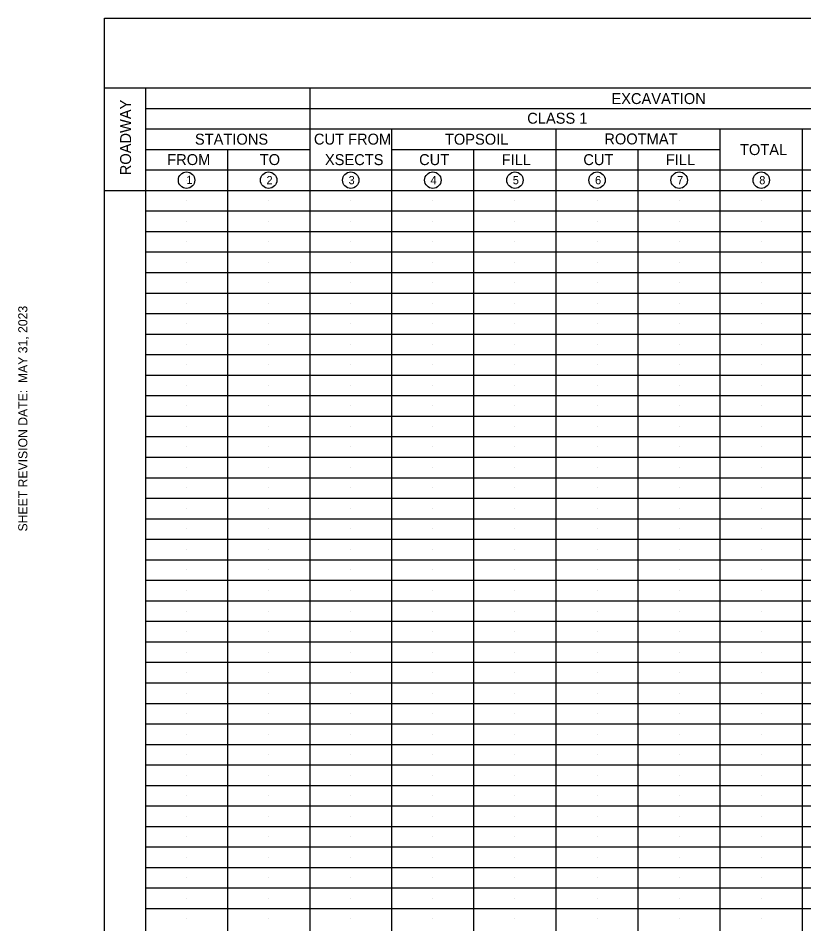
# Model space of a CAD drawing. Extents: x 1.3 to 38.6, y 0 to 21.1.
# Drawn here: x 1.3 to 9.92, y 11.12 to 21.06 of the extents above; entities that cross this region are included whole.
import ezdxf

# ---------------------------------------------------------------- set-up
doc = ezdxf.new("R2010")
doc.units = 0
for name, color, linetype in [('BORD-LINE', 7, 'Continuous'), ('CONS-LOGO', 7, 'Continuous'), ('TTLB-TEXT', 7, 'Continuous'), ('USER-LINE', 7, 'Continuous')]:
    doc.layers.add(name, color=color, linetype=linetype)

msp = doc.modelspace()

# ---------------------------------------------------------------- linework, layer by layer
at = {"layer": 'CONS-LOGO'}
for centre in [(3.1479, 19.278), (4.0479, 19.278), (4.9479, 19.278), (5.8479, 19.278), (6.7479, 19.278), (7.6479, 19.278), (8.5479, 19.278), (9.4479, 19.278)]:
    msp.add_circle(centre, 0.09, dxfattribs=at)
at = {"layer": 'TTLB-TEXT'}
for p, q in [((2.248, 1.1651), (2.248, 21.0551)), ((2.248, 21.055), (22.498, 21.055)), ((2.248, 20.29), (2.249, 20.29)), ((2.248, 20.29), (22.498, 20.29)), ((2.698, 20.29), (2.698, 1.165)), ((4.498, 20.2901), (4.498, 1.1651)), ((2.698, 20.065), (17.098, 20.065)), ((2.698, 19.84), (22.498, 19.84)), ((5.398, 4.54), (5.398, 19.8401)), ((7.198, 4.54), (7.198, 19.8401)), ((8.998, 4.54), (8.998, 19.8401)), ((9.898, 19.8401), (9.898, 4.54)), ((2.698, 19.615), (4.498, 19.615)), ((3.598, 19.6151), (3.598, 17.815)), ((5.398, 19.615), (8.998, 19.615)), ((6.298, 4.54), (6.298, 19.6151)), ((8.098, 4.54), (8.098, 19.6151)), ((2.698, 19.39), (22.498, 19.39)), ((2.248, 19.165), (22.498, 19.165)), ((2.698, 18.94), (22.498, 18.94)), ((2.698, 18.715), (22.498, 18.715)), ((2.698, 18.49), (22.498, 18.49)), ((2.698, 18.265), (22.498, 18.265)), ((2.698, 18.04), (22.498, 18.04)), ((2.698, 17.815), (22.498, 17.815)), ((3.598, 17.815), (3.598, 17.59)), ((2.698, 17.59), (22.498, 17.59)), ((3.598, 17.59), (3.598, 16.915)), ((2.698, 17.365), (22.498, 17.365)), ((2.698, 17.14), (22.498, 17.14)), ((2.698, 16.915), (22.498, 16.915)), ((3.598, 16.915), (3.598, 14.665)), ((2.698, 16.69), (22.498, 16.69)), ((2.698, 16.465), (22.498, 16.465)), ((2.698, 16.24), (22.498, 16.24)), ((2.698, 16.015), (22.498, 16.015)), ((2.698, 15.79), (22.498, 15.79)), ((2.698, 15.565), (22.498, 15.565)), ((2.698, 15.34), (22.498, 15.34)), ((2.698, 15.115), (22.498, 15.115)), ((2.698, 14.89), (22.498, 14.89)), ((2.698, 14.665), (22.498, 14.665)), ((3.598, 14.665), (3.598, 1.165)), ((2.698, 14.44), (22.498, 14.44)), ((2.698, 14.215), (22.498, 14.215)), ((2.698, 13.99), (22.498, 13.99)), ((2.698, 13.765), (22.498, 13.765)), ((2.698, 13.54), (22.498, 13.54)), ((2.698, 13.315), (22.498, 13.315)), ((2.698, 13.09), (22.498, 13.09)), ((2.698, 12.865), (22.498, 12.865)), ((2.698, 12.64), (22.498, 12.64)), ((2.698, 12.415), (22.498, 12.415)), ((2.698, 12.19), (22.498, 12.19)), ((2.698, 11.965), (22.498, 11.965)), ((2.698, 11.74), (22.498, 11.74)), ((2.698, 11.515), (22.498, 11.515)), ((2.698, 11.29), (22.498, 11.29))]:
    msp.add_line(p, q, dxfattribs=at)
at = {"layer": 'USER-LINE'}
for p, q in [((3.148, 19.5025), (3.148, 19.5025)), ((4.048, 19.5025), (4.048, 19.5025)), ((5.848, 19.5025), (5.848, 19.5025)), ((6.748, 19.5025), (6.748, 19.5025)), ((7.648, 19.5025), (7.648, 19.5025)), ((8.548, 19.5025), (8.548, 19.5025)), ((3.148, 19.2775), (3.148, 19.2775)), ((4.048, 19.2775), (4.048, 19.2775)), ((4.948, 19.2775), (4.948, 19.2775)), ((5.848, 19.2775), (5.848, 19.2775)), ((6.748, 19.2775), (6.748, 19.2775)), ((7.648, 19.2775), (7.648, 19.2775)), ((8.548, 19.2775), (8.548, 19.2775)), ((9.448, 19.2775), (9.448, 19.2775)), ((3.148, 19.0525), (3.148, 19.0525)), ((4.048, 19.0525), (4.048, 19.0525)), ((4.948, 19.0525), (4.948, 19.0525)), ((5.848, 19.0525), (5.848, 19.0525)), ((6.748, 19.0525), (6.748, 19.0525)), ((7.648, 19.0525), (7.648, 19.0525)), ((8.548, 19.0525), (8.548, 19.0525)), ((9.448, 19.0525), (9.448, 19.0525)), ((3.148, 18.8275), (3.148, 18.8275)), ((4.048, 18.8275), (4.048, 18.8275)), ((4.948, 18.8275), (4.948, 18.8275)), ((5.848, 18.8275), (5.848, 18.8275)), ((6.748, 18.8275), (6.748, 18.8275)), ((7.648, 18.8275), (7.648, 18.8275)), ((8.548, 18.8275), (8.548, 18.8275)), ((9.448, 18.8275), (9.448, 18.8275)), ((3.148, 18.6025), (3.148, 18.6025)), ((4.048, 18.6025), (4.048, 18.6025)), ((4.948, 18.6025), (4.948, 18.6025)), ((5.848, 18.6025), (5.848, 18.6025)), ((6.748, 18.6025), (6.748, 18.6025)), ((7.648, 18.6025), (7.648, 18.6025)), ((8.548, 18.6025), (8.548, 18.6025)), ((9.448, 18.6025), (9.448, 18.6025)), ((3.148, 18.3775), (3.148, 18.3775)), ((4.048, 18.3775), (4.048, 18.3775)), ((4.948, 18.3775), (4.948, 18.3775)), ((5.848, 18.3775), (5.848, 18.3775)), ((6.748, 18.3775), (6.748, 18.3775)), ((7.648, 18.3775), (7.648, 18.3775)), ((8.548, 18.3775), (8.548, 18.3775)), ((9.448, 18.3775), (9.448, 18.3775)), ((3.148, 18.1525), (3.148, 18.1525)), ((4.048, 18.1525), (4.048, 18.1525)), ((4.948, 18.1525), (4.948, 18.1525)), ((5.848, 18.1525), (5.848, 18.1525)), ((6.748, 18.1525), (6.748, 18.1525)), ((7.648, 18.1525), (7.648, 18.1525)), ((8.548, 18.1525), (8.548, 18.1525)), ((9.448, 18.1525), (9.448, 18.1525)), ((3.148, 17.9275), (3.148, 17.9275)), ((4.048, 17.9275), (4.048, 17.9275)), ((4.948, 17.9275), (4.948, 17.9275)), ((5.848, 17.9275), (5.848, 17.9275)), ((6.748, 17.9275), (6.748, 17.9275)), ((7.648, 17.9275), (7.648, 17.9275)), ((8.548, 17.9275), (8.548, 17.9275)), ((9.448, 17.9275), (9.448, 17.9275)), ((3.148, 17.7025), (3.148, 17.7025)), ((4.048, 17.7025), (4.048, 17.7025)), ((4.948, 17.7025), (4.948, 17.7025)), ((5.848, 17.7025), (5.848, 17.7025)), ((6.748, 17.7025), (6.748, 17.7025)), ((7.648, 17.7025), (7.648, 17.7025)), ((8.548, 17.7025), (8.548, 17.7025)), ((9.448, 17.7025), (9.448, 17.7025)), ((3.148, 17.4775), (3.148, 17.4775)), ((4.048, 17.4775), (4.048, 17.4775)), ((4.948, 17.4775), (4.948, 17.4775)), ((5.848, 17.4775), (5.848, 17.4775)), ((6.748, 17.4775), (6.748, 17.4775)), ((7.648, 17.4775), (7.648, 17.4775)), ((8.548, 17.4775), (8.548, 17.4775)), ((9.448, 17.4775), (9.448, 17.4775)), ((3.148, 17.2525), (3.148, 17.2525)), ((4.048, 17.2525), (4.048, 17.2525)), ((4.948, 17.2525), (4.948, 17.2525)), ((5.848, 17.2525), (5.848, 17.2525)), ((6.748, 17.2525), (6.748, 17.2525)), ((7.648, 17.2525), (7.648, 17.2525)), ((8.548, 17.2525), (8.548, 17.2525)), ((9.448, 17.2525), (9.448, 17.2525)), ((3.148, 17.0275), (3.148, 17.0275)), ((4.048, 17.0275), (4.048, 17.0275)), ((4.948, 17.0275), (4.948, 17.0275)), ((5.848, 17.0275), (5.848, 17.0275)), ((6.748, 17.0275), (6.748, 17.0275)), ((7.648, 17.0275), (7.648, 17.0275)), ((8.548, 17.0275), (8.548, 17.0275)), ((9.448, 17.0275), (9.448, 17.0275)), ((3.148, 16.8025), (3.148, 16.8025)), ((4.048, 16.8025), (4.048, 16.8025)), ((4.948, 16.8025), (4.948, 16.8025)), ((5.848, 16.8025), (5.848, 16.8025)), ((6.748, 16.8025), (6.748, 16.8025)), ((7.648, 16.8025), (7.648, 16.8025)), ((8.548, 16.8025), (8.548, 16.8025)), ((9.448, 16.8025), (9.448, 16.8025)), ((3.148, 16.5775), (3.148, 16.5775)), ((4.048, 16.5775), (4.048, 16.5775)), ((4.948, 16.5775), (4.948, 16.5775)), ((5.848, 16.5775), (5.848, 16.5775)), ((6.748, 16.5775), (6.748, 16.5775)), ((7.648, 16.5775), (7.648, 16.5775)), ((8.548, 16.5775), (8.548, 16.5775)), ((9.448, 16.5775), (9.448, 16.5775)), ((3.148, 16.3525), (3.148, 16.3525)), ((4.048, 16.3525), (4.048, 16.3525)), ((4.948, 16.3525), (4.948, 16.3525)), ((5.848, 16.3525), (5.848, 16.3525)), ((6.748, 16.3525), (6.748, 16.3525)), ((7.648, 16.3525), (7.648, 16.3525)), ((8.548, 16.3525), (8.548, 16.3525)), ((9.448, 16.3525), (9.448, 16.3525)), ((3.148, 16.1275), (3.148, 16.1275)), ((4.048, 16.1275), (4.048, 16.1275)), ((4.948, 16.1275), (4.948, 16.1275)), ((5.848, 16.1275), (5.848, 16.1275)), ((6.748, 16.1275), (6.748, 16.1275)), ((7.648, 16.1275), (7.648, 16.1275)), ((8.548, 16.1275), (8.548, 16.1275)), ((9.448, 16.1275), (9.448, 16.1275)), ((3.148, 15.9025), (3.148, 15.9025)), ((4.048, 15.9025), (4.048, 15.9025)), ((4.948, 15.9025), (4.948, 15.9025)), ((5.848, 15.9025), (5.848, 15.9025)), ((6.748, 15.9025), (6.748, 15.9025)), ((7.648, 15.9025), (7.648, 15.9025)), ((8.548, 15.9025), (8.548, 15.9025)), ((9.448, 15.9025), (9.448, 15.9025)), ((3.148, 15.6775), (3.148, 15.6775)), ((4.048, 15.6775), (4.048, 15.6775)), ((4.948, 15.6775), (4.948, 15.6775)), ((5.848, 15.6775), (5.848, 15.6775)), ((6.748, 15.6775), (6.748, 15.6775)), ((7.648, 15.6775), (7.648, 15.6775)), ((8.548, 15.6775), (8.548, 15.6775)), ((9.448, 15.6775), (9.448, 15.6775)), ((3.148, 15.4525), (3.148, 15.4525)), ((4.048, 15.4525), (4.048, 15.4525)), ((4.948, 15.4525), (4.948, 15.4525)), ((5.848, 15.4525), (5.848, 15.4525)), ((6.748, 15.4525), (6.748, 15.4525)), ((7.648, 15.4525), (7.648, 15.4525)), ((8.548, 15.4525), (8.548, 15.4525)), ((9.448, 15.4525), (9.448, 15.4525)), ((3.148, 15.2275), (3.148, 15.2275)), ((4.048, 15.2275), (4.048, 15.2275)), ((4.948, 15.2275), (4.948, 15.2275)), ((5.848, 15.2275), (5.848, 15.2275)), ((6.748, 15.2275), (6.748, 15.2275)), ((7.648, 15.2275), (7.648, 15.2275)), ((8.548, 15.2275), (8.548, 15.2275)), ((9.448, 15.2275), (9.448, 15.2275)), ((3.148, 15.0025), (3.148, 15.0025)), ((4.048, 15.0025), (4.048, 15.0025)), ((4.948, 15.0025), (4.948, 15.0025)), ((5.848, 15.0025), (5.848, 15.0025)), ((6.748, 15.0025), (6.748, 15.0025)), ((7.648, 15.0025), (7.648, 15.0025)), ((8.548, 15.0025), (8.548, 15.0025)), ((9.448, 15.0025), (9.448, 15.0025)), ((3.148, 14.7775), (3.148, 14.7775)), ((4.048, 14.7775), (4.048, 14.7775)), ((4.948, 14.7775), (4.948, 14.7775)), ((5.848, 14.7775), (5.848, 14.7775)), ((6.748, 14.7775), (6.748, 14.7775)), ((7.648, 14.7775), (7.648, 14.7775)), ((8.548, 14.7775), (8.548, 14.7775)), ((9.448, 14.7775), (9.448, 14.7775)), ((3.148, 14.5525), (3.148, 14.5525)), ((4.048, 14.5525), (4.048, 14.5525)), ((4.948, 14.5525), (4.948, 14.5525)), ((5.848, 14.5525), (5.848, 14.5525)), ((6.748, 14.5525), (6.748, 14.5525)), ((7.648, 14.5525), (7.648, 14.5525)), ((8.548, 14.5525), (8.548, 14.5525)), ((9.448, 14.5525), (9.448, 14.5525)), ((3.148, 14.3275), (3.148, 14.3275)), ((4.048, 14.3275), (4.048, 14.3275)), ((4.948, 14.3275), (4.948, 14.3275)), ((5.848, 14.3275), (5.848, 14.3275)), ((6.748, 14.3275), (6.748, 14.3275)), ((7.648, 14.3275), (7.648, 14.3275)), ((8.548, 14.3275), (8.548, 14.3275)), ((9.448, 14.3275), (9.448, 14.3275)), ((3.148, 14.1025), (3.148, 14.1025)), ((4.048, 14.1025), (4.048, 14.1025)), ((4.948, 14.1025), (4.948, 14.1025)), ((5.848, 14.1025), (5.848, 14.1025)), ((6.748, 14.1025), (6.748, 14.1025)), ((7.648, 14.1025), (7.648, 14.1025)), ((8.548, 14.1025), (8.548, 14.1025)), ((9.448, 14.1025), (9.448, 14.1025)), ((3.148, 13.8775), (3.148, 13.8775)), ((4.048, 13.8775), (4.048, 13.8775)), ((4.948, 13.8775), (4.948, 13.8775)), ((5.848, 13.8775), (5.848, 13.8775)), ((6.748, 13.8775), (6.748, 13.8775)), ((7.648, 13.8775), (7.648, 13.8775)), ((8.548, 13.8775), (8.548, 13.8775)), ((9.448, 13.8775), (9.448, 13.8775)), ((3.148, 13.6525), (3.148, 13.6525)), ((4.048, 13.6525), (4.048, 13.6525)), ((4.948, 13.6525), (4.948, 13.6525)), ((5.848, 13.6525), (5.848, 13.6525)), ((6.748, 13.6525), (6.748, 13.6525)), ((7.648, 13.6525), (7.648, 13.6525)), ((8.548, 13.6525), (8.548, 13.6525)), ((9.448, 13.6525), (9.448, 13.6525)), ((3.148, 13.4275), (3.148, 13.4275)), ((4.048, 13.4275), (4.048, 13.4275)), ((4.948, 13.4275), (4.948, 13.4275)), ((5.848, 13.4275), (5.848, 13.4275)), ((6.748, 13.4275), (6.748, 13.4275)), ((7.648, 13.4275), (7.648, 13.4275)), ((8.548, 13.4275), (8.548, 13.4275)), ((9.448, 13.4275), (9.448, 13.4275)), ((3.148, 13.2025), (3.148, 13.2025)), ((4.048, 13.2025), (4.048, 13.2025)), ((4.948, 13.2025), (4.948, 13.2025)), ((5.848, 13.2025), (5.848, 13.2025)), ((6.748, 13.2025), (6.748, 13.2025)), ((7.648, 13.2025), (7.648, 13.2025)), ((8.548, 13.2025), (8.548, 13.2025)), ((9.448, 13.2025), (9.448, 13.2025)), ((3.148, 12.9775), (3.148, 12.9775)), ((4.048, 12.9775), (4.048, 12.9775)), ((4.948, 12.9775), (4.948, 12.9775)), ((5.848, 12.9775), (5.848, 12.9775)), ((6.748, 12.9775), (6.748, 12.9775)), ((7.648, 12.9775), (7.648, 12.9775)), ((8.548, 12.9775), (8.548, 12.9775)), ((9.448, 12.9775), (9.448, 12.9775)), ((3.148, 12.7525), (3.148, 12.7525)), ((4.048, 12.7525), (4.048, 12.7525)), ((4.948, 12.7525), (4.948, 12.7525)), ((5.848, 12.7525), (5.848, 12.7525)), ((6.748, 12.7525), (6.748, 12.7525)), ((7.648, 12.7525), (7.648, 12.7525)), ((8.548, 12.7525), (8.548, 12.7525)), ((9.448, 12.7525), (9.448, 12.7525)), ((3.148, 12.5275), (3.148, 12.5275)), ((4.048, 12.5275), (4.048, 12.5275)), ((4.948, 12.5275), (4.948, 12.5275)), ((5.848, 12.5275), (5.848, 12.5275)), ((6.748, 12.5275), (6.748, 12.5275)), ((7.648, 12.5275), (7.648, 12.5275)), ((8.548, 12.5275), (8.548, 12.5275)), ((9.448, 12.5275), (9.448, 12.5275)), ((3.148, 12.3025), (3.148, 12.3025)), ((4.048, 12.3025), (4.048, 12.3025)), ((4.948, 12.3025), (4.948, 12.3025)), ((5.848, 12.3025), (5.848, 12.3025)), ((6.748, 12.3025), (6.748, 12.3025)), ((7.648, 12.3025), (7.648, 12.3025)), ((8.548, 12.3025), (8.548, 12.3025)), ((9.448, 12.3025), (9.448, 12.3025)), ((3.148, 12.0775), (3.148, 12.0775)), ((4.048, 12.0775), (4.048, 12.0775)), ((4.948, 12.0775), (4.948, 12.0775)), ((5.848, 12.0775), (5.848, 12.0775)), ((6.748, 12.0775), (6.748, 12.0775)), ((7.648, 12.0775), (7.648, 12.0775)), ((8.548, 12.0775), (8.548, 12.0775)), ((9.448, 12.0775), (9.448, 12.0775)), ((3.148, 11.8525), (3.148, 11.8525)), ((4.048, 11.8525), (4.048, 11.8525)), ((4.948, 11.8525), (4.948, 11.8525)), ((5.848, 11.8525), (5.848, 11.8525)), ((6.748, 11.8525), (6.748, 11.8525)), ((7.648, 11.8525), (7.648, 11.8525)), ((8.548, 11.8525), (8.548, 11.8525)), ((9.448, 11.8525), (9.448, 11.8525)), ((3.148, 11.6275), (3.148, 11.6275)), ((4.048, 11.6275), (4.048, 11.6275)), ((4.948, 11.6275), (4.948, 11.6275)), ((5.848, 11.6275), (5.848, 11.6275)), ((6.748, 11.6275), (6.748, 11.6275)), ((7.648, 11.6275), (7.648, 11.6275)), ((8.548, 11.6275), (8.548, 11.6275)), ((9.448, 11.6275), (9.448, 11.6275)), ((3.148, 11.4025), (3.148, 11.4025)), ((4.048, 11.4025), (4.048, 11.4025)), ((4.948, 11.4025), (4.948, 11.4025)), ((5.848, 11.4025), (5.848, 11.4025)), ((6.748, 11.4025), (6.748, 11.4025)), ((7.648, 11.4025), (7.648, 11.4025)), ((8.548, 11.4025), (8.548, 11.4025)), ((9.448, 11.4025), (9.448, 11.4025)), ((3.148, 11.1775), (3.148, 11.1775)), ((4.048, 11.1775), (4.048, 11.1775)), ((4.948, 11.1775), (4.948, 11.1775)), ((5.848, 11.1775), (5.848, 11.1775)), ((6.748, 11.1775), (6.748, 11.1775)), ((7.648, 11.1775), (7.648, 11.1775)), ((8.548, 11.1775), (8.548, 11.1775)), ((9.448, 11.1775), (9.448, 11.1775))]:
    msp.add_line(p, q, dxfattribs=at)

# ---------------------------------------------------------------- texts
at = {"layer": 'BORD-LINE'}
msp.add_text('SHEET REVISION DATE:  MAY 31, 2023', height=0.1, rotation=90, dxfattribs=at).set_placement((1.403, 15.425))
at = {"layer": 'CONS-LOGO'}
for s, height, p in [('EXCAVATION', 0.12, (7.8055, 20.1125)), ('CLASS 1', 0.12, (6.8825, 19.897)), ('STATIONS', 0.12, (3.2397, 19.6675)), ('CUT FROM', 0.12, (4.544, 19.668)), ('TOPSOIL', 0.12, (5.9803, 19.667)), ('ROOTMAT', 0.12, (7.7277, 19.67)), ('TOTAL', 0.12, (9.2149, 19.553)), ('FROM', 0.12, (2.936, 19.4435)), ('TO', 0.12, (3.9501, 19.4435)), ('XSECTS', 0.12, (4.6647, 19.443)), ('CUT', 0.12, (5.6973, 19.443)), ('FILL', 0.12, (6.6019, 19.4425)), ('CUT', 0.12, (7.4973, 19.443)), ('FILL', 0.12, (8.4019, 19.4425)), ('1', 0.09, (3.146, 19.236)), ('2', 0.09, (4.024, 19.233)), ('3', 0.09, (4.924, 19.233)), ('4', 0.09, (5.822, 19.233)), ('5', 0.09, (6.724, 19.233)), ('6', 0.09, (7.626, 19.233)), ('7', 0.09, (8.526, 19.233)), ('8', 0.09, (9.426, 19.233))]:
    msp.add_text(s, height=height, dxfattribs=at).set_placement(p)
msp.add_text('ROADWAY', height=0.12, rotation=90, dxfattribs=at).set_placement((2.5395, 19.3317))

doc.saveas('drawing.dxf')
